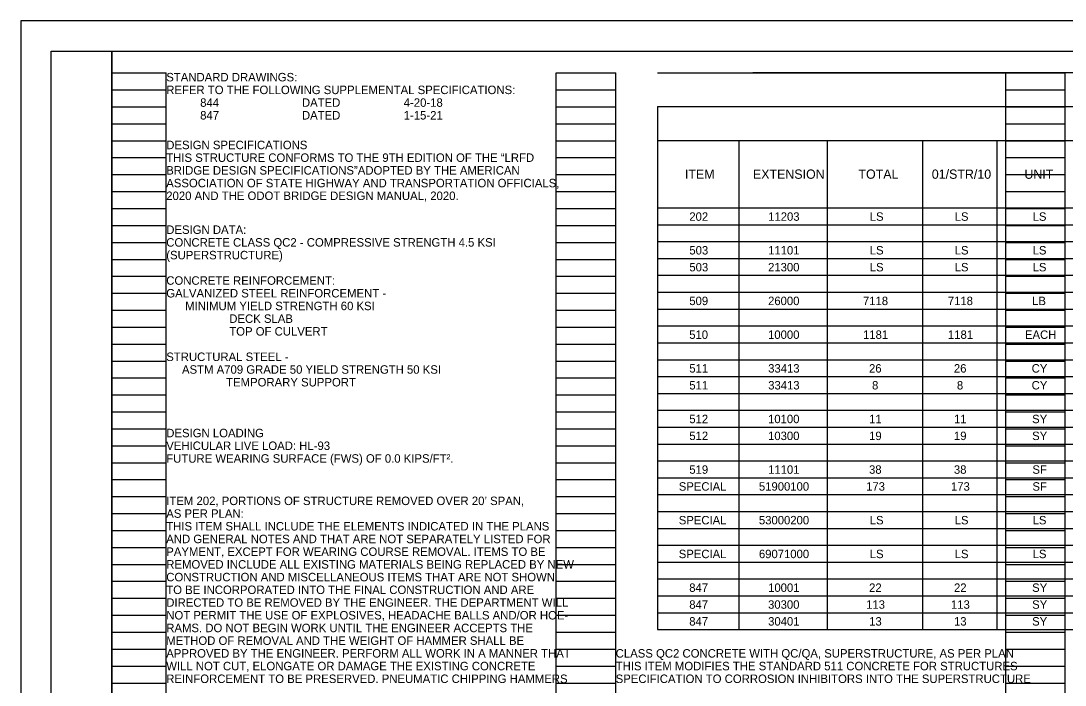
# Model space of a CAD drawing. Extents: x 0 to 34, y 0 to 22.
# Drawn here: x 0 to 17.24, y 11.03 to 22 of the extents above; entities that cross this region are included whole.
import ezdxf

# ---------------------------------------------------------------- set-up
doc = ezdxf.new("R2010")
doc.units = 0
for name, color, linetype in [('BR_P_Gen_Text', 7, 'Continuous'), ('SC_Scratch5', 7, 'Continuous'), ('SH_Border', 7, 'Continuous'), ('SH_Cut_Line', 7, 'Continuous'), ('SH_Masking', 7, 'Continuous'), ('SH_Text', 7, 'Continuous')]:
    doc.layers.add(name, color=color, linetype=linetype)

msp = doc.modelspace()

# ---------------------------------------------------------------- linework, layer by layer
at = {"layer": 'SC_Scratch5'}
for p, q in [((1.5, 0.98), (1.5, 21.14)), ((1.5, 21.14), (2.4, 21.14)), ((2.4, 0.98), (2.4, 21.14)), ((8.84, 0.98), (8.84, 21.14)), ((8.84, 21.14), (9.82, 21.14)), ((9.82, 0.98), (9.82, 21.14)), ((16.26, 0.98), (16.26, 21.14)), ((16.26, 21.14), (17.24, 21.14)), ((17.24, 0.98), (17.24, 21.14)), ((1.5, 20.86), (2.4, 20.86)), ((8.84, 20.86), (9.82, 20.86)), ((16.26, 20.86), (17.24, 20.86)), ((1.5, 20.58), (2.4, 20.58)), ((8.84, 20.58), (9.82, 20.58)), ((16.26, 20.58), (17.24, 20.58)), ((1.5, 20.3), (2.4, 20.3)), ((8.84, 20.3), (9.82, 20.3)), ((16.26, 20.3), (17.24, 20.3)), ((1.5, 20.02), (2.4, 20.02)), ((8.84, 20.02), (9.82, 20.02)), ((16.26, 20.02), (17.24, 20.02)), ((1.5, 19.74), (2.4, 19.74)), ((8.84, 19.74), (9.82, 19.74)), ((16.26, 19.74), (17.24, 19.74)), ((1.5, 19.46), (2.4, 19.46)), ((8.84, 19.46), (9.82, 19.46)), ((16.26, 19.46), (17.24, 19.46)), ((1.5, 19.18), (2.4, 19.18)), ((8.84, 19.18), (9.82, 19.18)), ((16.26, 19.18), (17.24, 19.18)), ((1.5, 18.9), (2.4, 18.9)), ((8.84, 18.9), (9.82, 18.9)), ((16.26, 18.9), (17.24, 18.9)), ((1.5, 18.62), (2.4, 18.62)), ((8.84, 18.62), (9.82, 18.62)), ((16.26, 18.62), (17.24, 18.62)), ((1.5, 18.34), (2.4, 18.34)), ((8.84, 18.34), (9.82, 18.34)), ((16.26, 18.34), (17.24, 18.34)), ((1.5, 18.06), (2.4, 18.06)), ((8.84, 18.06), (9.82, 18.06)), ((16.26, 18.06), (17.24, 18.06)), ((1.5, 17.78), (2.4, 17.78)), ((8.84, 17.78), (9.82, 17.78)), ((16.26, 17.78), (17.24, 17.78)), ((1.5, 17.5), (2.4, 17.5)), ((8.84, 17.5), (9.82, 17.5)), ((16.26, 17.5), (17.24, 17.5)), ((1.5, 17.22), (2.4, 17.22)), ((8.84, 17.22), (9.82, 17.22)), ((16.26, 17.22), (17.24, 17.22)), ((1.5, 16.94), (2.4, 16.94)), ((8.84, 16.94), (9.82, 16.94)), ((16.26, 16.94), (17.24, 16.94)), ((1.5, 16.66), (2.4, 16.66)), ((8.84, 16.66), (9.82, 16.66)), ((16.26, 16.66), (17.24, 16.66)), ((1.5, 16.38), (2.4, 16.38)), ((8.84, 16.38), (9.82, 16.38)), ((16.26, 16.38), (17.24, 16.38)), ((1.5, 16.1), (2.4, 16.1)), ((8.84, 16.1), (9.82, 16.1)), ((16.26, 16.1), (17.24, 16.1)), ((1.5, 15.82), (2.4, 15.82)), ((8.84, 15.82), (9.82, 15.82)), ((16.26, 15.82), (17.24, 15.82)), ((1.5, 15.54), (2.4, 15.54)), ((8.84, 15.54), (9.82, 15.54)), ((16.26, 15.54), (17.24, 15.54)), ((1.5, 15.26), (2.4, 15.26)), ((8.84, 15.26), (9.82, 15.26)), ((16.26, 15.26), (17.24, 15.26)), ((1.5, 14.98), (2.4, 14.98)), ((8.84, 14.98), (9.82, 14.98)), ((16.26, 14.98), (17.24, 14.98)), ((1.5, 14.7), (2.4, 14.7)), ((8.84, 14.7), (9.82, 14.7)), ((16.26, 14.7), (17.24, 14.7)), ((1.5, 14.42), (2.4, 14.42)), ((8.84, 14.42), (9.82, 14.42)), ((16.26, 14.42), (17.24, 14.42)), ((1.5, 14.14), (2.4, 14.14)), ((8.84, 14.14), (9.82, 14.14)), ((16.26, 14.14), (17.24, 14.14)), ((1.5, 13.86), (2.4, 13.86)), ((8.84, 13.86), (9.82, 13.86)), ((16.26, 13.86), (17.24, 13.86)), ((1.5, 13.58), (2.4, 13.58)), ((8.84, 13.58), (9.82, 13.58)), ((16.26, 13.58), (17.24, 13.58)), ((1.5, 13.3), (2.4, 13.3)), ((8.84, 13.3), (9.82, 13.3)), ((16.26, 13.3), (17.24, 13.3)), ((1.5, 13.02), (2.4, 13.02)), ((8.84, 13.02), (9.82, 13.02)), ((16.26, 13.02), (17.24, 13.02)), ((1.5, 12.74), (2.4, 12.74)), ((8.84, 12.74), (9.82, 12.74)), ((16.26, 12.74), (17.24, 12.74)), ((1.5, 12.46), (2.4, 12.46)), ((8.84, 12.46), (9.82, 12.46)), ((16.26, 12.46), (17.24, 12.46)), ((1.5, 12.18), (2.4, 12.18)), ((8.84, 12.18), (9.82, 12.18)), ((16.26, 12.18), (17.24, 12.18)), ((1.5, 11.9), (2.4, 11.9)), ((8.84, 11.9), (9.82, 11.9)), ((16.26, 11.9), (17.24, 11.9)), ((1.5, 11.62), (2.4, 11.62)), ((8.84, 11.62), (9.82, 11.62)), ((16.26, 11.62), (17.24, 11.62)), ((1.5, 11.34), (2.4, 11.34)), ((8.84, 11.34), (9.82, 11.34)), ((16.26, 11.34), (17.24, 11.34)), ((1.5, 11.06), (2.4, 11.06)), ((8.84, 11.06), (9.82, 11.06)), ((16.26, 11.06), (17.24, 11.06))]:
    msp.add_line(p, q, dxfattribs=at)
at = {"layer": 'SH_Border'}
for points in [[(0.5, 21.5), (1.5, 21.5), (1.5, 0.5), (0.5, 0.5)], [(1.5, 21.5), (33.5, 21.5), (33.5, 0.5), (1.5, 0.5)]]:
    msp.add_lwpolyline(points, close=True, dxfattribs=at)
at = {"layer": 'SH_Cut_Line'}
msp.add_lwpolyline([(0, 0), (34, 0), (34, 22), (0, 22)], close=True, dxfattribs=at)
at = {"layer": 'SH_Masking'}
for p, q in [((10.509, 21.14), (16.328, 21.14)), ((17.905, 21.14), (12.085, 21.14))]:
    msp.add_line(p, q, dxfattribs=at)
at = {"layer": 'SH_Text'}
for p, q in [((10.509, 20.583), (29.689, 20.583)), ((10.509, 20.583), (10.509, 11.943)), ((10.509, 20.025), (29.689, 20.025)), ((11.853, 20.025), (11.853, 11.943)), ((13.312, 20.025), (13.312, 11.943)), ((14.886, 20.025), (14.886, 11.943)), ((16.115, 20.025), (16.115, 11.943)), ((10.509, 18.91), (29.689, 18.91)), ((10.509, 18.632), (29.689, 18.632)), ((10.509, 18.353), (29.689, 18.353)), ((10.509, 18.074), (29.689, 18.074)), ((10.509, 17.796), (29.689, 17.796)), ((10.509, 17.517), (29.689, 17.517)), ((10.509, 17.238), (29.689, 17.238)), ((10.509, 16.96), (29.689, 16.96)), ((10.509, 16.681), (29.689, 16.681)), ((10.509, 16.402), (29.689, 16.402)), ((10.509, 16.123), (29.689, 16.123)), ((10.509, 15.845), (29.689, 15.845)), ((10.509, 15.566), (29.689, 15.566)), ((10.509, 15.287), (29.689, 15.287)), ((10.509, 15.009), (29.689, 15.009)), ((10.509, 14.73), (29.689, 14.73)), ((10.509, 14.451), (29.689, 14.451)), ((10.509, 14.173), (29.689, 14.173)), ((10.509, 13.894), (29.689, 13.894)), ((10.509, 13.615), (29.689, 13.615)), ((10.509, 13.337), (29.689, 13.337)), ((10.509, 13.058), (29.689, 13.058)), ((10.509, 12.779), (29.689, 12.779)), ((10.509, 12.5), (29.689, 12.5)), ((10.509, 12.222), (29.689, 12.222)), ((10.509, 11.943), (29.689, 11.943))]:
    msp.add_line(p, q, dxfattribs=at)

# ---------------------------------------------------------------- texts
at = {"layer": 'BR_P_Gen_Text'}
for s, p in [('DESIGN SPECIFICATIONS', (2.4, 19.88)), ('THIS STRUCTURE CONFORMS TO THE 9TH EDITION OF THE “LRFD ', (2.4, 19.67)), ('BRIDGE DESIGN SPECIFICATIONS”ADOPTED BY THE AMERICAN ', (2.4, 19.46)), ('ASSOCIATION OF STATE HIGHWAY AND TRANSPORTATION OFFICIALS, ', (2.4, 19.25)), ('2020 AND THE ODOT BRIDGE DESIGN MANUAL, 2020.', (2.4, 19.04)), ('DESIGN LOADING', (2.4, 15.12)), ('VEHICULAR LIVE LOAD: HL-93', (2.4, 14.91)), ('FUTURE WEARING SURFACE (FWS) OF 0.0 KIPS/FT².', (2.4, 14.7)), ('ITEM 202, PORTIONS OF STRUCTURE REMOVED OVER 20’ SPAN, ', (2.4, 14)), ('I', (2.4, 14)), ('AS PER PLAN: ', (2.4, 13.79)), ('THIS ITEM SHALL INCLUDE THE ELEMENTS INDICATED IN THE PLANS ', (2.4, 13.58)), ('AND GENERAL NOTES AND THAT ARE NOT SEPARATELY LISTED FOR ', (2.4, 13.37)), ('PAYMENT, EXCEPT FOR WEARING COURSE REMOVAL. ITEMS TO BE ', (2.4, 13.16)), ('REMOVED INCLUDE ALL EXISTING MATERIALS BEING REPLACED BY NEW ', (2.4, 12.95)), ('CONSTRUCTION AND MISCELLANEOUS ITEMS THAT ARE NOT SHOWN ', (2.4, 12.74)), ('TO BE INCORPORATED INTO THE FINAL CONSTRUCTION AND ARE ', (2.4, 12.53)), ('DIRECTED TO BE REMOVED BY THE ENGINEER. THE DEPARTMENT WILL ', (2.4, 12.32)), ('NOT PERMIT THE USE OF EXPLOSIVES, HEADACHE BALLS AND/OR HOE-', (2.4, 12.11)), ('RAMS. DO NOT BEGIN WORK UNTIL THE ENGINEER ACCEPTS THE ', (2.4, 11.9)), ('METHOD OF REMOVAL AND THE WEIGHT OF HAMMER SHALL BE ', (2.4, 11.69)), ('APPROVED BY THE ENGINEER. PERFORM ALL WORK IN A MANNER THAT ', (2.4, 11.48)), ('CLASS QC2 CONCRETE WITH QC/QA, SUPERSTRUCTURE, AS PER PLAN', (9.82, 11.48)), ('WILL NOT CUT, ELONGATE OR DAMAGE THE EXISTING CONCRETE ', (2.4, 11.27)), ('THIS ITEM MODIFIES THE STANDARD 511 CONCRETE FOR STRUCTURES ', (9.82, 11.27)), ('REINFORCEMENT TO BE PRESERVED. PNEUMATIC CHIPPING HAMMERS ', (2.4, 11.06)), ('SPECIFICATION TO CORROSION INHIBITORS INTO THE SUPERSTRUCTURE ', (9.82, 11.06))]:
    msp.add_text(s, height=0.14, dxfattribs=at).set_placement(p)
at = {"layer": 'SH_Text'}
for s, height, p in [('STANDARD DRAWINGS:', 0.14, (2.4, 21)), ('REFER TO THE FOLLOWING SUPPLEMENTAL SPECIFICATIONS:', 0.14, (2.4, 20.79)), ('844', 0.14, (2.96, 20.58)), ('DATED', 0.14, (4.64, 20.58)), ('4-20-18', 0.14, (6.32, 20.58)), ('847', 0.14, (2.96, 20.37)), ('DATED', 0.14, (4.64, 20.37)), ('1-15-21', 0.14, (6.32, 20.37)), ('ITEM', 0.1533, (10.963, 19.391)), ('EXTENSION', 0.1533, (12.086, 19.391)), ('TOTAL', 0.1533, (13.828, 19.391)), ('01/STR/10', 0.1533, (15.039, 19.391)), ('UNIT', 0.1533, (16.568, 19.391)), ('202', 0.1393, (11.036, 18.697)), ('11203', 0.1393, (12.338, 18.697)), ('LS', 0.1393, (14.015, 18.697)), ('LS', 0.1393, (15.417, 18.697)), ('LS', 0.1393, (16.704, 18.697)), ('DESIGN DATA:', 0.14, (2.4, 18.48)), ('CONCRETE CLASS QC2 - COMPRESSIVE STRENGTH 4.5 KSI ', 0.14, (2.4, 18.27)), ('503', 0.1393, (11.037, 18.14)), ('11101', 0.1393, (12.337, 18.14)), ('LS', 0.1393, (14.015, 18.14)), ('LS', 0.1393, (15.417, 18.14)), ('LS', 0.1393, (16.704, 18.14)), ('(SUPERSTRUCTURE)', 0.14, (2.4, 18.06)), ('503', 0.1393, (11.037, 17.861)), ('21300', 0.1393, (12.336, 17.861)), ('LS', 0.1393, (14.015, 17.861)), ('LS', 0.1393, (15.417, 17.861)), ('LS', 0.1393, (16.704, 17.861)), ('CONCRETE REINFORCEMENT:', 0.14, (2.4, 17.64)), ('GALVANIZED STEEL REINFORCEMENT -', 0.14, (2.4, 17.43)), ('509', 0.1393, (11.036, 17.304)), ('26000', 0.1393, (12.336, 17.304)), ('7118', 0.1393, (13.903, 17.304)), ('7118', 0.1393, (15.304, 17.304)), ('LB', 0.1393, (16.696, 17.304)), ('      MINIMUM YIELD STRENGTH 60 KSI', 0.14, (2.4, 17.22)), ('                    DECK SLAB', 0.14, (2.4, 17.01)), ('                    TOP OF CULVERT', 0.14, (2.4, 16.8)), ('510', 0.1393, (11.034, 16.746)), ('10000', 0.1393, (12.336, 16.746)), ('1181', 0.1393, (13.904, 16.746)), ('1181', 0.1393, (15.306, 16.746)), ('EACH', 0.1393, (16.578, 16.746)), ('STRUCTURAL STEEL - ', 0.14, (2.4, 16.38)), ('     ASTM A709 GRADE 50 YIELD STRENGTH 50 KSI', 0.14, (2.4, 16.17)), ('511', 0.1393, (11.036, 16.189)), ('33413', 0.1393, (12.338, 16.189)), ('26', 0.1393, (14.003, 16.189)), ('26', 0.1393, (15.404, 16.189)), ('CY', 0.1393, (16.688, 16.189)), ('                   TEMPORARY SUPPORT', 0.14, (2.4, 15.96)), ('511', 0.1393, (11.036, 15.91)), ('33413', 0.1393, (12.338, 15.91)), ('8', 0.139, (14.053, 15.91)), ('8', 0.139, (15.454, 15.91)), ('CY', 0.1393, (16.688, 15.91)), ('512', 0.1393, (11.036, 15.353)), ('10100', 0.1393, (12.336, 15.353)), ('11', 0.1393, (14.004, 15.353)), ('11', 0.1393, (15.406, 15.353)), ('SY', 0.1393, (16.696, 15.353)), ('512', 0.1393, (11.036, 15.074)), ('10300', 0.1393, (12.336, 15.074)), ('19', 0.1393, (14.004, 15.074)), ('19', 0.1393, (15.405, 15.074)), ('SY', 0.1393, (16.696, 15.074)), ('519', 0.1393, (11.036, 14.517)), ('11101', 0.1393, (12.337, 14.517)), ('38', 0.1393, (14.003, 14.517)), ('38', 0.1393, (15.404, 14.517)), ('SF', 0.1393, (16.701, 14.517)), ('SPECIAL', 0.1393, (10.862, 14.238)), ('51900100', 0.1393, (12.185, 14.238)), ('173', 0.1393, (13.955, 14.238)), ('173', 0.1393, (15.356, 14.238)), ('SF', 0.1393, (16.701, 14.238)), ('SPECIAL', 0.1393, (10.862, 13.681)), ('53000200', 0.1393, (12.185, 13.681)), ('LS', 0.1393, (14.015, 13.681)), ('LS', 0.1393, (15.417, 13.681)), ('LS', 0.1393, (16.704, 13.681)), ('SPECIAL', 0.1393, (10.862, 13.123)), ('69071000', 0.1393, (12.185, 13.123)), ('LS', 0.1393, (14.015, 13.123)), ('LS', 0.1393, (15.417, 13.123)), ('LS', 0.1393, (16.704, 13.123)), ('847', 0.1393, (11.035, 12.566)), ('10001', 0.1393, (12.337, 12.566)), ('22', 0.1393, (14.004, 12.566)), ('22', 0.1393, (15.406, 12.566)), ('SY', 0.1393, (16.696, 12.566)), ('847', 0.1393, (11.035, 12.287)), ('30300', 0.1393, (12.336, 12.287)), ('113', 0.1393, (13.955, 12.287)), ('113', 0.1393, (15.356, 12.287)), ('SY', 0.1393, (16.696, 12.287)), ('847', 0.1393, (11.035, 12.009)), ('30401', 0.1393, (12.337, 12.009)), ('13', 0.1393, (14.005, 12.009)), ('13', 0.1393, (15.406, 12.009)), ('SY', 0.1393, (16.696, 12.009))]:
    msp.add_text(s, height=height, dxfattribs=at).set_placement(p)

doc.saveas('drawing.dxf')
